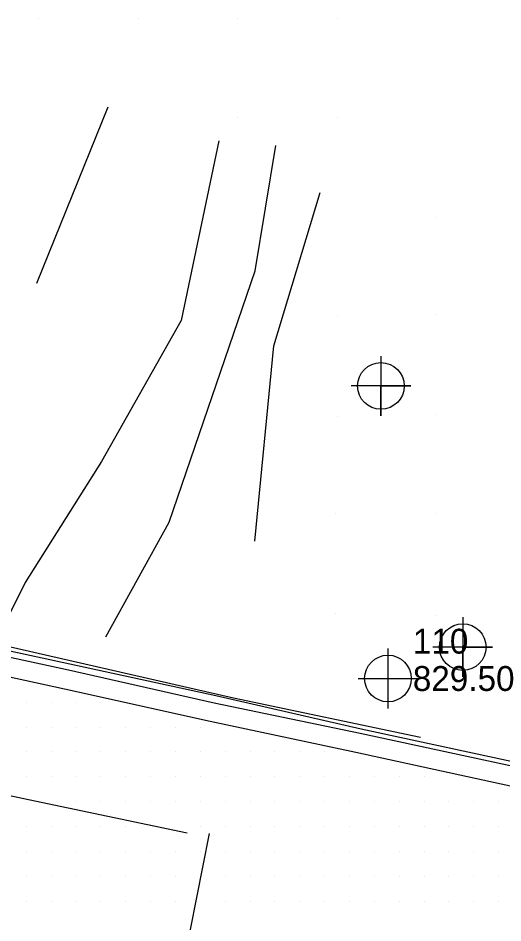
# Model space of a CAD drawing. Extents: x 1762120 to 1766775, y 709485 to 712965.
# Drawn here: x 1763187.9 to 1763236.7, y 712549.1 to 712640 of the extents above; entities that cross this region are included whole.
import ezdxf

# ---------------------------------------------------------------- set-up
doc = ezdxf.new("R2010")
doc.units = 0
for name, color, linetype in [('Cogo Default Point CELL', 7, 'Continuous'), ('COGO Default Point Elevation', 7, 'Continuous'), ('COGO Default Point Number', 7, 'Continuous'), ('Exist DTM Breakline', 7, 'Continuous'), ('Exist DTM Drainline', 7, 'Continuous'), ('Exist DTM QL2 LIDAR Elevation Point', 7, 'Continuous'), ('Exist DTM Regular Point CELL', 7, 'Continuous'), ('Exist DTM Scan Elevation Point', 7, 'Continuous'), ('Exist Roads Curbs', 7, 'Continuous'), ('Exist Roads EOP', 7, 'Continuous'), ('Exist Roads EOT', 7, 'Continuous')]:
    doc.layers.add(name, color=color, linetype=linetype)

msp = doc.modelspace()

# ---------------------------------------------------------------- linework, layer by layer
at = {"layer": 'Cogo Default Point CELL'}
for points in [[(1763225.118, 712576.625), (1763225.118, 712573.625)], [(1763222.118, 712573.625), (1763225.118, 712573.625)], [(1763225.118, 712573.625), (1763228.118, 712573.625)], [(1763225.118, 712573.625), (1763225.118, 712570.625)]]:
    msp.add_lwpolyline(points, dxfattribs=at)
msp.add_circle((1763225.118, 712573.625), 2.344, dxfattribs=at)
at = {"layer": 'Exist DTM Breakline'}
msp.add_line((1763196.939, 712631.064), (1763189.771, 712613.315), dxfattribs=at)
for points in [[(1763208.103, 712627.664), (1763204.31, 712609.612), (1763196.316, 712595.421), (1763188.649, 712583.258), (1763186.939, 712579.819)], [(1763196.756, 712577.829), (1763203.121, 712589.346), (1763211.762, 712614.601), (1763213.848, 712627.208)], [(1763211.728, 712587.44), (1763213.646, 712607.073), (1763218.302, 712622.471)], [(1763228.396, 712567.706), (1763209.574, 712571.649), (1763183.194, 712577.672), (1763154.339, 712583.753), (1763109.288, 712593.456), (1763089.475, 712597.586), (1763087.749, 712600.046)]]:
    msp.add_lwpolyline(points, dxfattribs=at)
at = {"layer": 'Exist DTM Drainline'}
msp.add_lwpolyline([(1763089.461, 712596.666), (1763105.186, 712593.393), (1763119.823, 712590.226), (1763134.436, 712587.072), (1763149.077, 712583.936), (1763163.767, 712580.768), (1763178.414, 712577.646), (1763193.012, 712574.483), (1763207.655, 712571.168), (1763222.327, 712568.147), (1763236.948, 712564.982), (1763251.578, 712561.802), (1763266.222, 712558.686), (1763274.477, 712556.87), (1763299.09, 712551.53)], dxfattribs=at)
at = {"layer": 'Exist DTM QL2 LIDAR Elevation Point'}
for p, q in [((1763190, 712640), (1763190, 712640)), ((1763200, 712640), (1763200, 712640)), ((1763210, 712640), (1763210, 712640)), ((1763220, 712640), (1763220, 712640)), ((1763210, 712630), (1763210, 712630)), ((1763220, 712630), (1763220, 712630)), ((1763230, 712620), (1763230, 712620)), ((1763220, 712610), (1763220, 712610)), ((1763229.883, 712610.17), (1763229.883, 712610.17)), ((1763220, 712600), (1763220, 712600)), ((1763229.883, 712600.169), (1763229.883, 712600.169)), ((1763219.882, 712590.168), (1763219.882, 712590.168)), ((1763229.883, 712590.168), (1763229.883, 712590.168)), ((1763219.882, 712580.166), (1763219.882, 712580.166)), ((1763230, 712580), (1763230, 712580))]:
    msp.add_line(p, q, dxfattribs=at)
at = {"layer": 'Exist DTM Regular Point CELL'}
for points in [[(1763224.409, 712606.025), (1763224.409, 712600.025), (1763224.409, 712603.025), (1763227.409, 712603.025), (1763221.409, 712603.025)], [(1763232.637, 712579.783), (1763232.637, 712573.783), (1763232.637, 712576.783), (1763235.637, 712576.783), (1763229.637, 712576.783)]]:
    msp.add_lwpolyline(points, dxfattribs=at)
for centre in [(1763224.409, 712603.025), (1763232.637, 712576.783)]:
    msp.add_circle(centre, 2.344, dxfattribs=at)
at = {"layer": 'Exist DTM Scan Elevation Point'}
for p, q in [((1763188.75, 712571.25), (1763188.75, 712571.25)), ((1763191.25, 712571.25), (1763191.25, 712571.25)), ((1763193.75, 712571.25), (1763193.75, 712571.25)), ((1763196.25, 712571.25), (1763196.25, 712571.25)), ((1763188.75, 712568.75), (1763188.75, 712568.75)), ((1763191.25, 712568.75), (1763191.25, 712568.75)), ((1763193.75, 712568.75), (1763193.75, 712568.75)), ((1763196.25, 712568.75), (1763196.25, 712568.75)), ((1763198.75, 712568.75), (1763198.75, 712568.75)), ((1763201.25, 712568.75), (1763201.25, 712568.75)), ((1763203.75, 712568.75), (1763203.75, 712568.75)), ((1763206.25, 712568.75), (1763206.25, 712568.75)), ((1763188.75, 712566.25), (1763188.75, 712566.25)), ((1763191.25, 712566.25), (1763191.25, 712566.25)), ((1763193.75, 712566.25), (1763193.75, 712566.25)), ((1763196.25, 712566.25), (1763196.25, 712566.25)), ((1763198.75, 712566.25), (1763198.75, 712566.25)), ((1763201.25, 712566.25), (1763201.25, 712566.25)), ((1763203.75, 712566.25), (1763203.75, 712566.25)), ((1763206.25, 712566.25), (1763206.25, 712566.25)), ((1763208.75, 712566.25), (1763208.75, 712566.25)), ((1763211.25, 712566.25), (1763211.25, 712566.25)), ((1763213.75, 712566.25), (1763213.75, 712566.25)), ((1763216.25, 712566.25), (1763216.25, 712566.25)), ((1763218.75, 712566.25), (1763218.75, 712566.25)), ((1763188.75, 712563.75), (1763188.75, 712563.75)), ((1763191.25, 712563.75), (1763191.25, 712563.75)), ((1763193.75, 712563.75), (1763193.75, 712563.75)), ((1763196.25, 712563.75), (1763196.25, 712563.75)), ((1763198.75, 712563.75), (1763198.75, 712563.75)), ((1763201.25, 712563.75), (1763201.25, 712563.75)), ((1763203.75, 712563.75), (1763203.75, 712563.75)), ((1763206.25, 712563.75), (1763206.25, 712563.75)), ((1763208.75, 712563.75), (1763208.75, 712563.75)), ((1763211.25, 712563.75), (1763211.25, 712563.75)), ((1763213.75, 712563.75), (1763213.75, 712563.75)), ((1763216.25, 712563.75), (1763216.25, 712563.75)), ((1763218.75, 712563.75), (1763218.75, 712563.75)), ((1763221.25, 712563.75), (1763221.25, 712563.75)), ((1763223.75, 712563.75), (1763223.75, 712563.75)), ((1763226.25, 712563.75), (1763226.25, 712563.75)), ((1763228.75, 712563.75), (1763228.75, 712563.75)), ((1763193.75, 712561.25), (1763193.75, 712561.25)), ((1763196.25, 712561.25), (1763196.25, 712561.25)), ((1763198.75, 712561.25), (1763198.75, 712561.25)), ((1763201.25, 712561.25), (1763201.25, 712561.25)), ((1763203.75, 712561.25), (1763203.75, 712561.25)), ((1763206.25, 712561.25), (1763206.25, 712561.25)), ((1763208.75, 712561.25), (1763208.75, 712561.25)), ((1763211.25, 712561.25), (1763211.25, 712561.25)), ((1763213.75, 712561.25), (1763213.75, 712561.25)), ((1763216.25, 712561.25), (1763216.25, 712561.25)), ((1763218.75, 712561.25), (1763218.75, 712561.25)), ((1763221.25, 712561.25), (1763221.25, 712561.25)), ((1763223.75, 712561.25), (1763223.75, 712561.25)), ((1763226.25, 712561.25), (1763226.25, 712561.25)), ((1763228.75, 712561.25), (1763228.75, 712561.25)), ((1763231.25, 712561.25), (1763231.25, 712561.25)), ((1763233.75, 712561.25), (1763233.75, 712561.25)), ((1763236.25, 712561.25), (1763236.25, 712561.25)), ((1763188.75, 712558.75), (1763188.75, 712558.75)), ((1763191.25, 712558.75), (1763191.25, 712558.75)), ((1763193.75, 712558.75), (1763193.75, 712558.75)), ((1763196.25, 712558.75), (1763196.25, 712558.75)), ((1763198.75, 712558.75), (1763198.75, 712558.75)), ((1763206.25, 712558.75), (1763206.25, 712558.75)), ((1763208.75, 712558.75), (1763208.75, 712558.75)), ((1763211.25, 712558.75), (1763211.25, 712558.75)), ((1763213.75, 712558.75), (1763213.75, 712558.75)), ((1763216.25, 712558.75), (1763216.25, 712558.75)), ((1763218.75, 712558.75), (1763218.75, 712558.75)), ((1763221.25, 712558.75), (1763221.25, 712558.75)), ((1763223.75, 712558.75), (1763223.75, 712558.75)), ((1763226.25, 712558.75), (1763226.25, 712558.75)), ((1763228.75, 712558.75), (1763228.75, 712558.75)), ((1763231.25, 712558.75), (1763231.25, 712558.75)), ((1763233.75, 712558.75), (1763233.75, 712558.75)), ((1763236.25, 712558.75), (1763236.25, 712558.75)), ((1763188.75, 712556.25), (1763188.75, 712556.25)), ((1763191.25, 712556.25), (1763191.25, 712556.25)), ((1763193.75, 712556.25), (1763193.75, 712556.25)), ((1763196.25, 712556.25), (1763196.25, 712556.25)), ((1763198.75, 712556.25), (1763198.75, 712556.25)), ((1763201.25, 712556.25), (1763201.25, 712556.25)), ((1763203.75, 712556.25), (1763203.75, 712556.25)), ((1763206.25, 712556.25), (1763206.25, 712556.25)), ((1763208.75, 712556.25), (1763208.75, 712556.25)), ((1763211.25, 712556.25), (1763211.25, 712556.25)), ((1763213.75, 712556.25), (1763213.75, 712556.25)), ((1763216.25, 712556.25), (1763216.25, 712556.25)), ((1763218.75, 712556.25), (1763218.75, 712556.25)), ((1763221.25, 712556.25), (1763221.25, 712556.25)), ((1763223.75, 712556.25), (1763223.75, 712556.25)), ((1763226.25, 712556.25), (1763226.25, 712556.25)), ((1763228.75, 712556.25), (1763228.75, 712556.25)), ((1763231.25, 712556.25), (1763231.25, 712556.25)), ((1763233.75, 712556.25), (1763233.75, 712556.25)), ((1763236.25, 712556.25), (1763236.25, 712556.25)), ((1763188.75, 712553.75), (1763188.75, 712553.75)), ((1763191.25, 712553.75), (1763191.25, 712553.75)), ((1763193.75, 712553.75), (1763193.75, 712553.75)), ((1763196.25, 712553.75), (1763196.25, 712553.75)), ((1763198.75, 712553.75), (1763198.75, 712553.75)), ((1763201.25, 712553.75), (1763201.25, 712553.75)), ((1763203.75, 712553.75), (1763203.75, 712553.75)), ((1763208.75, 712553.75), (1763208.75, 712553.75)), ((1763211.25, 712553.75), (1763211.25, 712553.75)), ((1763213.75, 712553.75), (1763213.75, 712553.75)), ((1763216.25, 712553.75), (1763216.25, 712553.75)), ((1763218.75, 712553.75), (1763218.75, 712553.75)), ((1763221.25, 712553.75), (1763221.25, 712553.75)), ((1763223.75, 712553.75), (1763223.75, 712553.75)), ((1763226.25, 712553.75), (1763226.25, 712553.75)), ((1763228.75, 712553.75), (1763228.75, 712553.75)), ((1763231.25, 712553.75), (1763231.25, 712553.75)), ((1763233.75, 712553.75), (1763233.75, 712553.75)), ((1763236.25, 712553.75), (1763236.25, 712553.75)), ((1763188.75, 712551.25), (1763188.75, 712551.25)), ((1763191.25, 712551.25), (1763191.25, 712551.25)), ((1763193.75, 712551.25), (1763193.75, 712551.25)), ((1763196.25, 712551.25), (1763196.25, 712551.25)), ((1763198.75, 712551.25), (1763198.75, 712551.25)), ((1763201.25, 712551.25), (1763201.25, 712551.25)), ((1763203.75, 712551.25), (1763203.75, 712551.25)), ((1763208.75, 712551.25), (1763208.75, 712551.25)), ((1763211.25, 712551.25), (1763211.25, 712551.25)), ((1763213.75, 712551.25), (1763213.75, 712551.25)), ((1763216.25, 712551.25), (1763216.25, 712551.25)), ((1763218.75, 712551.25), (1763218.75, 712551.25)), ((1763221.25, 712551.25), (1763221.25, 712551.25)), ((1763223.75, 712551.25), (1763223.75, 712551.25)), ((1763226.25, 712551.25), (1763226.25, 712551.25)), ((1763228.75, 712551.25), (1763228.75, 712551.25)), ((1763231.25, 712551.25), (1763231.25, 712551.25)), ((1763233.75, 712551.25), (1763233.75, 712551.25)), ((1763236.25, 712551.25), (1763236.25, 712551.25))]:
    msp.add_line(p, q, dxfattribs=at)
at = {"layer": 'Exist Roads Curbs'}
msp.add_lwpolyline([(1763089.553, 712597.315), (1763105.321, 712594.032), (1763119.962, 712590.885), (1763134.574, 712587.756), (1763149.21, 712584.592), (1763163.905, 712581.39), (1763178.545, 712578.238), (1763193.143, 712575.098), (1763207.826, 712571.919), (1763222.426, 712568.578), (1763237.047, 712565.423), (1763251.674, 712562.23), (1763266.336, 712559.194), (1763273.697, 712557.482)], dxfattribs=at)
at = {"layer": 'Exist Roads EOP'}
msp.add_lwpolyline([(1763090.11, 712594.46), (1763104.774, 712591.438), (1763119.418, 712588.303), (1763134.062, 712585.226), (1763148.688, 712582.014), (1763163.357, 712578.925), (1763177.998, 712575.776), (1763192.607, 712572.575), (1763207.239, 712569.338), (1763221.89, 712566.224), (1763236.512, 712563.025), (1763251.153, 712559.894), (1763265.788, 712556.737), (1763272.938, 712555.128), (1763281.095, 712553.402), (1763287.44, 712552.09), (1763292.203, 712550.988), (1763300.15, 712549.23)], dxfattribs=at)
at = {"layer": 'Exist Roads EOT'}
for points in [[(1763056.38, 712588.88), (1763078.41, 712584.54), (1763099.11, 712580.31), (1763112.53, 712577.49), (1763127.57, 712574.41), (1763143.94, 712571.01), (1763168.52, 712565.81), (1763188.97, 712561.48), (1763204.93, 712558.1)], [(1763207.15, 712558.05), (1763204.61, 712545.19), (1763202, 712531.95), (1763200.82, 712526.17)]]:
    msp.add_lwpolyline(points, dxfattribs=at)

# ---------------------------------------------------------------- texts
at = {"layer": 'COGO Default Point Elevation'}
msp.add_text('829.50', height=2.5, dxfattribs=at).set_placement((1763227.618, 712572.375))
at = {"layer": 'COGO Default Point Number'}
msp.add_text('110', height=2.5, dxfattribs=at).set_placement((1763227.618, 712576.125))

doc.saveas('drawing.dxf')
